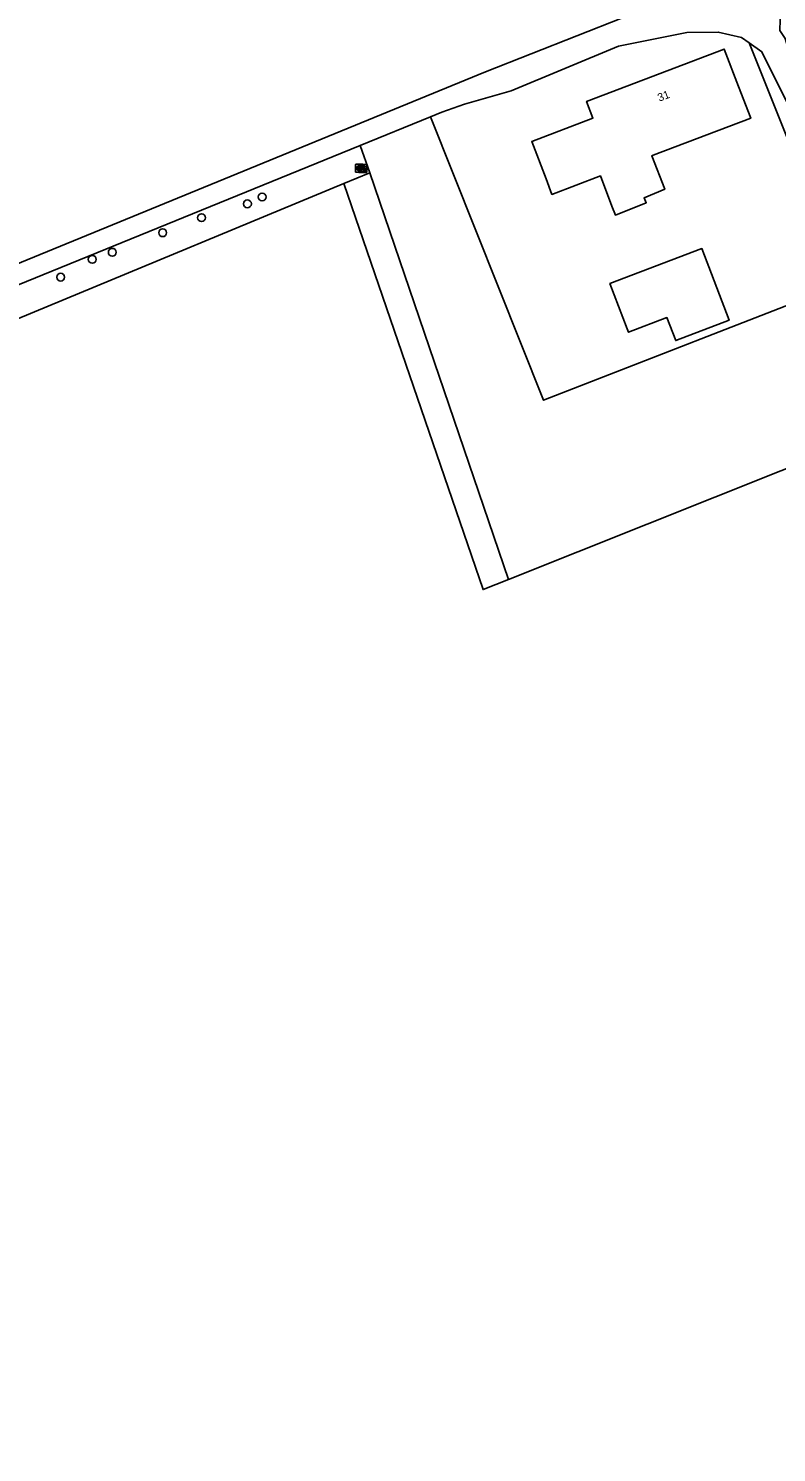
# Model space of a CAD drawing. Extents: x 162510 to 163918, y 388494 to 389774.
# Drawn here: x 162708.2 to 162801.7, y 389384 to 389562 of the extents above; entities that cross this region are included whole.
import ezdxf

# ---------------------------------------------------------------- set-up
doc = ezdxf.new("R2010")
doc.units = 0
for name, color, linetype in [('IMGEO_Boom', 7, 'Continuous'), ('IMGEO_Erf', 7, 'Continuous'), ('IMGEO_Grasland_agrarisch', 7, 'Continuous'), ('IMGEO_Grasland_overig', 7, 'Continuous'), ('IMGEO_Kast', 7, 'Continuous'), ('IMGEO_Loofbos', 7, 'Continuous'), ('IMGEO_Pand', 7, 'Continuous'), ('IMGEO_Pand_nummerreeks', 7, 'Continuous'), ('IMGEO_Rijbaan_lokaal_onverhard', 7, 'Continuous'), ('IMGEO_Rioolput', 7, 'Continuous')]:
    doc.layers.add(name, color=color, linetype=linetype)

msp = doc.modelspace()

# ---------------------------------------------------------------- linework, layer by layer
at = {"layer": 'IMGEO_Boom'}
for centre in [(162735.58, 389540.04), (162737.42, 389540.9), (162729.85, 389538.31), (162725, 389536.43), (162716.2, 389533.1), (162718.7, 389533.99), (162712.25, 389530.88)]:
    msp.add_circle(centre, 0.489, dxfattribs=at)
at = {"layer": 'IMGEO_Erf'}
msp.add_lwpolyline([(162675.54, 389519.85), (162679.52, 389521.34), (162765.33, 389556.56), (162788.12, 389565.57), (162797.51, 389568.67), (162797.54, 389568.68)], dxfattribs=at)
for points in [[(162798.23, 389560.18), (162797.3, 389560.83), (162794.38, 389561.5), (162790.45, 389561.45), (162781.93, 389559.73), (162768.52, 389554.18), (162762.7, 389552.48), (162759.86, 389551.5), (162758.46, 389550.93), (162772.54, 389515.5), (162810.25, 389530.17)], [(162771.09, 389547.84), (162778.73, 389550.74), (162777.93, 389552.85), (162795.14, 389559.39), (162796.92, 389554.71), (162798.43, 389550.73), (162786.27, 389546.11), (162786.07, 389546.03), (162787.69, 389541.87), (162785.12, 389540.78), (162785.38, 389540.17), (162781.54, 389538.63), (162781.11, 389539.76), (162779.67, 389543.54), (162773.6, 389541.23), (162772.87, 389543.16)], [(162780.85, 389530.07), (162792.35, 389534.44), (162795.74, 389525.49), (162789.07, 389522.96), (162787.98, 389525.83), (162783.16, 389524), (162782.99, 389524.43)]]:
    msp.add_lwpolyline(points, close=True, dxfattribs=at)
at = {"layer": 'IMGEO_Grasland_agrarisch'}
msp.add_lwpolyline([(162812.35, 389537.53), (162810.6, 389540.81), (162809.47, 389543.32), (162808.53, 389545.75), (162805.1, 389552.99), (162802.98, 389552.67), (162799.84, 389559.06), (162798.23, 389560.18), (162810.25, 389530.17), (162772.54, 389515.5), (162758.46, 389550.93), (162749.68, 389547.35), (162750.86, 389543.91), (162768.2, 389493.08), (162785.51, 389500), (162827.33, 389516.71), (162830.73, 389522.5), (162828.02, 389524.54), (162823.62, 389527.41), (162818.85, 389530.65), (162814.84, 389534.48)], close=True, dxfattribs=at)
msp.add_lwpolyline([(162827.33, 389516.71), (162785.51, 389500), (162768.2, 389493.08), (162765.02, 389491.82), (162747.64, 389542.57), (162673.74, 389511.91), (162660.64, 389486.29), (162645.79, 389460.14), (162630.34, 389430.94), (162620.12, 389411.44), (162611.16, 389387.65), (162603.73, 389364.73), (162600.09, 389349.34), (162595.22, 389323.12), (162589.65, 389295.27), (162587.18, 389279.33)], dxfattribs=at)
at = {"layer": 'IMGEO_Grasland_overig'}
msp.add_lwpolyline([(162750.86, 389543.91), (162747.64, 389542.57), (162765.02, 389491.82), (162768.2, 389493.08)], close=True, dxfattribs=at)
at = {"layer": 'IMGEO_Kast'}
for p, q in [((162749.48, 389544.02), (162749.48, 389544.86)), ((162749.48, 389544.86), (162749.48, 389544.02)), ((162749.56, 389544.94), (162750.4, 389544.94)), ((162750.4, 389544.94), (162749.56, 389544.94)), ((162750.41, 389543.94), (162749.57, 389543.94)), ((162749.57, 389543.94), (162750.41, 389543.94)), ((162750.48, 389544.87), (162750.48, 389544.03)), ((162750.48, 389544.03), (162750.48, 389544.87))]:
    msp.add_line(p, q, dxfattribs=at)
for points in [[(162749.68, 389544.73), (162750.28, 389544.73), (162750.28, 389544.65), (162749.68, 389544.65), (162749.68, 389544.73)], [(162749.68, 389544.56), (162750.28, 389544.56), (162750.28, 389544.07), (162749.68, 389544.07), (162749.68, 389544.56)]]:
    msp.add_lwpolyline(points, dxfattribs=at)
msp.add_circle((162749.76, 389544.41), 0.0377, dxfattribs=at)
for centre, start, end in [((162749.56, 389544.86), 92.4484, 184.2845), ((162749.56, 389544.86), 92.4484, 184.2845), ((162749.56, 389544.02), 182.4484, 274.2845), ((162749.56, 389544.02), 182.4484, 274.2845), ((162750.41, 389544.86), 2.4484, 94.2845), ((162750.41, 389544.86), 2.4484, 94.2845), ((162750.41, 389544.02), 272.4484, 4.2845), ((162750.41, 389544.02), 272.4484, 4.2845)]:
    msp.add_arc(centre, 0.0779, start, end, dxfattribs=at)
at = {"layer": 'IMGEO_Loofbos'}
for points in [[(162750.86, 389543.91), (162749.68, 389547.35), (162678.22, 389518.21)], [(162665.88, 389515.76), (162666.43, 389514.84), (162667.11, 389513.87), (162668.18, 389513.17), (162669.13, 389512.35), (162669.72, 389510.24), (162673.74, 389511.91), (162747.64, 389542.57), (162750.86, 389543.91)]]:
    msp.add_lwpolyline(points, dxfattribs=at)
at = {"layer": 'IMGEO_Pand'}
for points in [[(162798.43, 389550.73), (162796.92, 389554.71), (162795.14, 389559.39), (162777.93, 389552.85), (162778.73, 389550.74), (162771.09, 389547.84), (162772.87, 389543.16), (162773.6, 389541.23), (162779.67, 389543.54), (162781.11, 389539.76), (162781.54, 389538.63), (162785.38, 389540.17), (162785.12, 389540.78), (162787.69, 389541.87), (162786.07, 389546.03), (162786.27, 389546.11)], [(162789.07, 389522.96), (162795.74, 389525.49), (162792.35, 389534.44), (162780.85, 389530.07), (162782.99, 389524.43), (162783.16, 389524), (162787.98, 389525.83)]]:
    msp.add_lwpolyline(points, close=True, dxfattribs=at)
at = {"layer": 'IMGEO_Rijbaan_lokaal_onverhard'}
for points in [[(162749.68, 389547.35), (162758.46, 389550.93), (162759.86, 389551.5), (162762.7, 389552.48), (162768.52, 389554.18), (162781.93, 389559.73), (162790.45, 389561.45), (162794.38, 389561.5), (162797.3, 389560.83), (162798.23, 389560.18), (162799.84, 389559.06), (162802.98, 389552.67), (162805.1, 389552.99), (162802.74, 389560.7), (162802.08, 389561.71), (162802.2, 389565.73), (162800.82, 389569.76), (162797.54, 389568.68), (162797.51, 389568.67), (162788.12, 389565.57), (162765.33, 389556.56), (162679.52, 389521.34), (162675.54, 389519.85)], [(162678.22, 389518.21), (162749.68, 389547.35)]]:
    msp.add_lwpolyline(points, dxfattribs=at)
at = {"layer": 'IMGEO_Rioolput'}
for p, q in [((162749.07, 389544.07), (162749.07, 389544.93)), ((162749.14, 389545), (162749.99, 389545)), ((162749.99, 389544), (162749.14, 389544)), ((162749.32, 389544.49), (162749.32, 389544.51)), ((162749.76, 389544.46), (162749.36, 389544.46)), ((162749.37, 389544.54), (162749.77, 389544.54)), ((162749.55, 389544.78), (162749.58, 389544.78)), ((162749.58, 389544.22), (162749.55, 389544.22)), ((162749.81, 389544.51), (162749.81, 389544.49)), ((162750.07, 389544.93), (162750.07, 389544.07))]:
    msp.add_line(p, q, dxfattribs=at)
for points in [[(162749.07, 389544.07), (162749.07, 389544.93)], [(162749.14, 389545), (162749.99, 389545)], [(162749.99, 389544), (162749.14, 389544)], [(162750.07, 389544.93), (162750.07, 389544.07)]]:
    msp.add_lwpolyline(points, dxfattribs=at)
for centre, radius, start, end in [((162749.14, 389544.92), 0.0765, 91.552, 178.448), ((162749.14, 389544.92), 0.0765, 91.552, 178.448), ((162749.14, 389544.07), 0.0765, 181.552, 268.448), ((162749.14, 389544.07), 0.0765, 181.552, 268.448), ((162749.37, 389544.5), 0.0403, 85.8775, 175.7526), ((162749.36, 389544.49), 0.0366, 178.938, 274.7102), ((162749.77, 389544.5), 0.043, 264.8664, 352.4533), ((162749.77, 389544.5), 0.0386, 1.7309, 96.639), ((162749.99, 389544.92), 0.0765, 1.552, 88.448), ((162749.99, 389544.92), 0.0765, 1.552, 88.448), ((162749.99, 389544.07), 0.0765, 271.552, 358.448), ((162749.99, 389544.07), 0.0765, 271.552, 358.448)]:
    msp.add_arc(centre, radius, start, end, dxfattribs=at)
for centre, major_axis, ratio, start_param, end_param in [((162749.55, 389544.5), (-0.387, 0.002), 0.722429, 4.712389, 7.853982), ((162749.58, 389544.5), (-0.39, 0.002), 0.717154, 1.570796, 4.712389)]:
    msp.add_ellipse(centre, major_axis=major_axis, ratio=ratio, start_param=start_param, end_param=end_param, dxfattribs=at)

# ---------------------------------------------------------------- texts
at = {"layer": 'IMGEO_Pand_nummerreeks'}
msp.add_text('31', height=1, rotation=20.7926, dxfattribs=at).set_placement((162787.03, 389552.8))

doc.saveas('drawing.dxf')
